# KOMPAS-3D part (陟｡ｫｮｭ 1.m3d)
File: created 29.01.2016 13:47:21, last saved 25.07.2016 11:28:05.
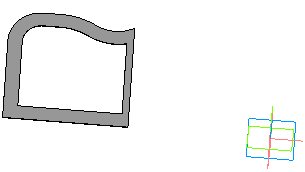
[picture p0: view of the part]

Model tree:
1. Эскиз:1
2. Операция выдавливания:1
     Толщина стенки 2 = 18; Расстояние 1 = 0.6
3. Эскиз:2
4. Вырезать элемент выдавливания:1
     Толщина стенки 2 = 2; Расстояние 1 = 30
5. Эскиз:3
6. Операция выдавливания:2
     Расстояние 1 = 0.6
7. Эскиз:4
8. Операция выдавливания:3
     Расстояние 1 = 0.6
9. Эскиз:5
10. Вырезать элемент выдавливания:2
     Расстояние 1 = 10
